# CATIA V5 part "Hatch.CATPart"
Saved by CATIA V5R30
Part number: Hatch
Material "Aluminium": density 2710 kg/m3, Young's modulus 7e+10 Pa, Poisson ratio 0.346, thermal expansion 2.36e-05 1/K
Bounding box of the stored display mesh (mm): x -50 to 50, y -50 to 50, z 0 to 1
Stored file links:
  D:\OneDrive\OneDrive - Carleton University\Courses\aero2001\Design Project\3D Models\Hatch.CATPart
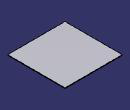
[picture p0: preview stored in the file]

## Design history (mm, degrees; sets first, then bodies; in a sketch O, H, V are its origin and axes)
Body1 (main body), material "Aluminium"
  Sketch1 on xy-plane, origin (0, 0, 0), H (1, 0, 0), V (0, 1, 0)
    line L1 (50, 50) -> (50, -50)
    line L2 (50, -50) -> (-50, -50)
    line L3 (-50, -50) -> (-50, 50)
    line L4 (-50, 50) -> (50, 50)
    distance L2 L4 = 100
    distance L1 L3 = 100
    vertical: L1 V, L3 V
    horizontal: L2 H, L4 H
    equidistance: L1 L3 O, L2 L4 O
  Pad1: profile Sketch1, direction (0, 0, 1), length 1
